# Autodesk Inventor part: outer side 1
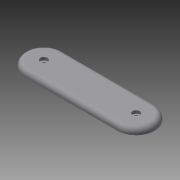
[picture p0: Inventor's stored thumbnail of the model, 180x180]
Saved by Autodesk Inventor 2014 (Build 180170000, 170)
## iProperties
Created: 2015-01
Part Number: outer side 1
Material: Generic
Document SubType Name: Modeling
Designer: Drano
Density: 1 g/cm^3
Appearance: Default
Author: Drano
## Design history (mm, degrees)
sketch "Sketch1"
  geometry: L1 (-39.389, -16.629)-(37.611, -16.629); L2 (-39.389, 14.371)-(37.611, 14.371); C1 r 1.5 at (-39.389, -1.129); C2 r 1.5 at (37.611, -1.129); A1 r 15.5 centre (37.611, -1.129) between (37.611, -16.629) and (37.611, 14.371); A2 r 15.5 centre (-39.389, -1.129) between (-39.389, 14.371) and (-39.389, -16.629); 1 further point
  constraints: 4 centre point, 4 end point, 4 point on circle
extrude "Extrusion1" new body sketch "Sketch1" distance "d0" = 5; taper "d1" = 0 deg
fillet "Fillet1" dims "d2" = 4
feature "Lip1" dims "d3" = 2.5, "d4" = 1.5, "d5" = 0, "d6" = 0, "d7" = 0, "d8" = 0
feature "Lip2" dims "d9" = 2.5, "d10" = 1.5, "d11" = 0, "d12" = 0, "d13" = 0, "d14" = 0
body "Solid1"
